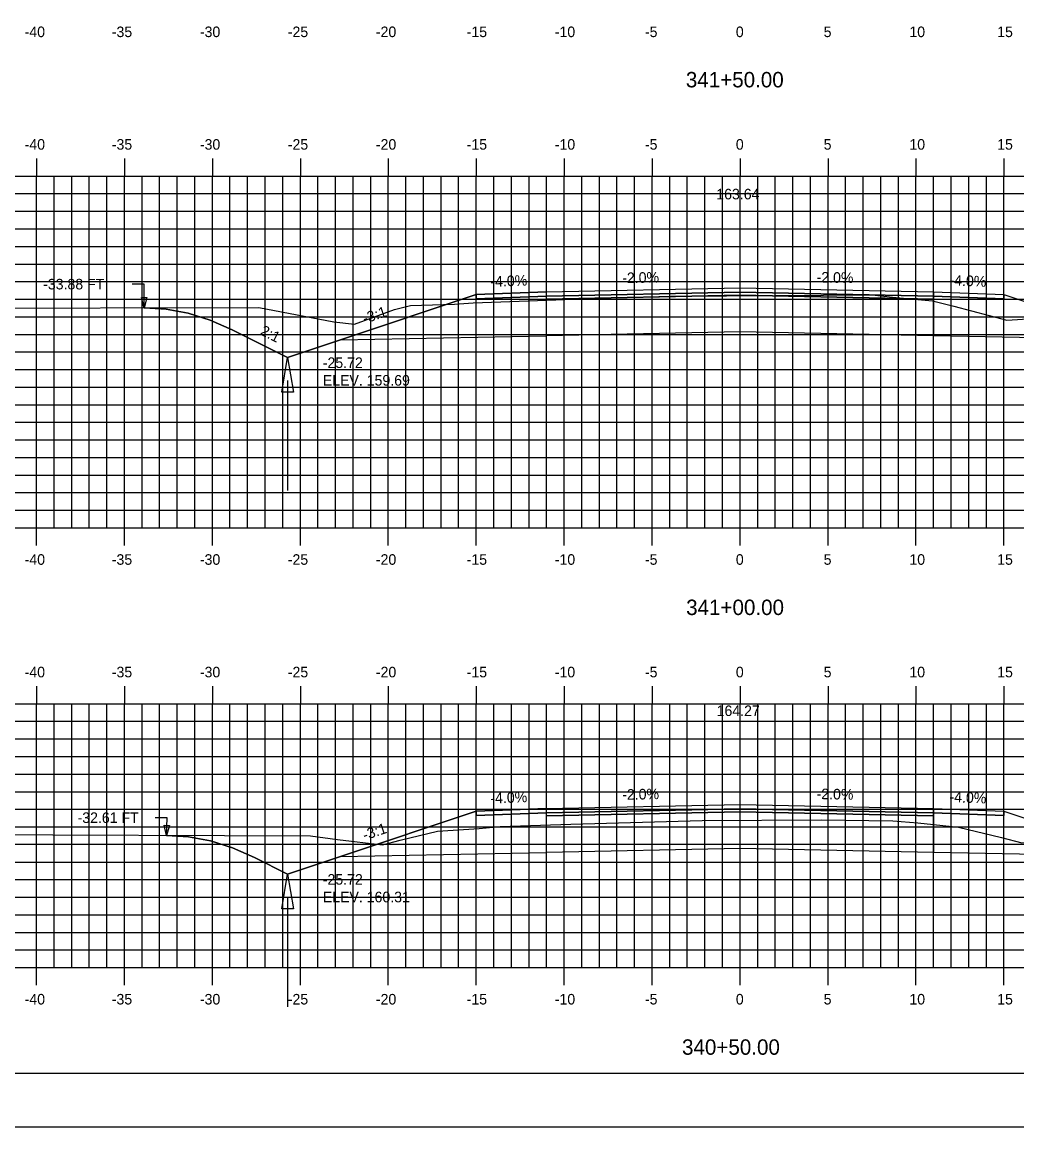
# Model space of a CAD drawing. Extents: x 1142976 to 1143146, y 608981 to 609091.
# Drawn here: x 1143018.7 to 1143075.3, y 608981.3 to 609044.1 of the extents above; entities that cross this region are included whole.
import ezdxf

# ---------------------------------------------------------------- set-up
doc = ezdxf.new("R2010")
doc.units = 0
for name, color, linetype in [('ANNOTATION', 7, 'Continuous'), ('BORDER', 7, 'Continuous'), ('D_Drainage_Ditch_Line', 7, 'Continuous'), ('D_Roadway_Centerline', 7, 'Continuous'), ('D_Roadway_Centerline_Text', 7, 'Continuous'), ('D_Roadway_Edge_Shoulder', 7, 'Continuous'), ('D_Roadway_Edge_TW', 7, 'Continuous'), ('D_Roadway_Pavement', 7, 'Continuous'), ('D_Roadway_SlopeLines', 7, 'Continuous'), ('D_Roadway_SubGrade', 7, 'Continuous'), ('D_Text_Standard', 7, 'Continuous'), ('H_V ANNOTATION', 7, 'Continuous'), ('MAJOR', 7, 'Continuous'), ('MINOR', 7, 'Continuous'), ('PLOT BOUNDARY', 7, 'Continuous'), ('S_Roadway_Centerline', 7, 'Continuous')]:
    doc.layers.add(name, color=color, linetype=linetype)

msp = doc.modelspace()

# ---------------------------------------------------------------- linework, layer by layer
for points in [[(1143025.688, 609027.847), (1143026.938, 609027.77), (1143028.188, 609027.537), (1143029.438, 609027.147), (1143030.688, 609026.6), (1143033.842, 609025.023), (1143036.842, 609026.023), (1143044.566, 609028.598), (1143044.567, 609028.598), (1143048.567, 609028.758), (1143059.567, 609028.978), (1143070.567, 609028.758), (1143074.567, 609028.598), (1143082.29, 609026.023), (1143085.29, 609025.023), (1143087.35, 609026.053), (1143088.6, 609026.598), (1143089.85, 609026.983), (1143091.1, 609027.207), (1143092.35, 609027.271)], [(1143026.958, 608997.852), (1143028.208, 608997.769), (1143029.458, 608997.532), (1143030.708, 608997.139), (1143031.958, 608996.592), (1143033.842, 608995.649), (1143036.842, 608996.649), (1143044.566, 608999.224), (1143044.567, 608999.224), (1143048.567, 608999.384), (1143059.567, 608999.604), (1143070.567, 608999.384), (1143074.567, 608999.224), (1143082.29, 608996.65), (1143085.29, 608995.65), (1143086.768, 608996.388), (1143088.018, 608996.934), (1143089.268, 608997.32), (1143090.518, 608997.546), (1143091.768, 608997.614)]]:
    msp.add_lwpolyline(points)
at = {"layer": 'BORDER'}
msp.add_lwpolyline([(1142984.567, 608984.335), (1143144.567, 608984.335), (1143144.567, 609089.335), (1142984.567, 609089.335)], close=True, dxfattribs=at)
at = {"layer": 'D_Drainage_Ditch_Line'}
for p, q in [((1143033.842, 609023.711), (1143033.842, 609017.467)), ((1143033.842, 608994.337), (1143033.842, 608988.094))]:
    msp.add_line(p, q, dxfattribs=at)
for points in [[(1143034.17, 609023.055), (1143033.514, 609023.055), (1143033.842, 609025.023)], [(1143034.17, 608993.681), (1143033.514, 608993.681), (1143033.842, 608995.649)]]:
    msp.add_lwpolyline(points, close=True, dxfattribs=at)
at = {"layer": 'D_Roadway_Edge_Shoulder'}
for points in [[(1143048.567, 609028.758), (1143044.567, 609028.598), (1143044.567, 609028.348), (1143048.567, 609028.508)], [(1143070.567, 609028.758), (1143074.567, 609028.598), (1143074.567, 609028.348), (1143070.567, 609028.508)], [(1143048.567, 608999.384), (1143044.567, 608999.224), (1143044.567, 608998.974), (1143048.567, 608999.134)], [(1143070.567, 608999.384), (1143074.567, 608999.224), (1143074.567, 608998.974), (1143070.567, 608999.134)]]:
    msp.add_lwpolyline(points, close=True, dxfattribs=at)
at = {"layer": 'D_Roadway_Edge_TW'}
for points in [[(1143048.567, 609028.508), (1143048.567, 609028.758), (1143059.567, 609028.978), (1143070.567, 609028.758), (1143070.567, 609028.508), (1143059.567, 609028.728)], [(1143048.567, 608999.134), (1143048.567, 608999.384), (1143059.567, 608999.604), (1143070.567, 608999.384), (1143070.567, 608999.134), (1143059.567, 608999.354)]]:
    msp.add_lwpolyline(points, close=True, dxfattribs=at)
at = {"layer": 'D_Roadway_Pavement'}
for points in [[(1143048.567, 609028.341), (1143048.567, 609028.508), (1143059.567, 609028.728), (1143070.567, 609028.508), (1143070.567, 609028.341), (1143059.567, 609028.561)], [(1143048.567, 608998.967), (1143048.567, 608999.134), (1143059.567, 608999.354), (1143070.567, 608999.134), (1143070.567, 608998.967), (1143059.567, 608999.187)]]:
    msp.add_lwpolyline(points, close=True, dxfattribs=at)
at = {"layer": 'D_Roadway_SlopeLines'}
for points in [[(1143033.842, 609025.023), (1143030.688, 609026.6), (1143029.438, 609027.147), (1143028.188, 609027.537), (1143026.938, 609027.77), (1143025.688, 609027.847)], [(1143036.842, 609026.023), (1143033.842, 609025.023)], [(1143033.842, 608995.649), (1143031.958, 608996.592), (1143030.708, 608997.139), (1143029.458, 608997.532), (1143028.208, 608997.769), (1143026.958, 608997.852)], [(1143036.842, 608996.649), (1143033.842, 608995.649)]]:
    msp.add_lwpolyline(points, dxfattribs=at)
at = {"layer": 'D_Roadway_SubGrade'}
for points in [[(1143048.567, 609028.341), (1143048.567, 609028.508), (1143044.567, 609028.348), (1143044.567, 609028.598), (1143044.566, 609028.598), (1143036.842, 609026.023), (1143048.567, 609026.258)], [(1143070.567, 609028.341), (1143070.567, 609028.508), (1143074.567, 609028.348), (1143074.567, 609028.598), (1143074.567, 609028.598), (1143082.29, 609026.023), (1143070.567, 609026.258)], [(1143048.567, 609026.258), (1143048.567, 609028.341), (1143059.567, 609028.561), (1143070.567, 609028.341), (1143070.567, 609026.258), (1143059.567, 609026.478)], [(1143048.567, 608998.967), (1143048.567, 608999.134), (1143044.567, 608998.974), (1143044.567, 608999.224), (1143044.566, 608999.224), (1143036.842, 608996.649), (1143048.567, 608996.884)], [(1143048.567, 608996.884), (1143048.567, 608998.967), (1143059.567, 608999.187), (1143070.567, 608998.967), (1143070.567, 608996.884), (1143059.567, 608997.104)], [(1143070.567, 608998.967), (1143070.567, 608999.134), (1143074.567, 608998.974), (1143074.567, 608999.224), (1143074.567, 608999.224), (1143082.29, 608996.65), (1143070.567, 608996.884)]]:
    msp.add_lwpolyline(points, close=True, dxfattribs=at)
at = {"layer": 'D_Text_Standard'}
for points in [[(1143025.688, 609027.85), (1143025.683, 609029.19), (1143025.003, 609029.19)], [(1143026.958, 608997.842), (1143026.986, 608998.856), (1143026.306, 608998.856)]]:
    msp.add_lwpolyline(points, dxfattribs=at)
for points in [[(1143025.688, 609027.85), (1143025.54, 609028.432), (1143025.831, 609028.433)], [(1143026.958, 608997.842), (1143026.828, 608998.427), (1143027.119, 608998.419)]]:
    msp.add_lwpolyline(points, close=True, dxfattribs=at)
at = {"layer": 'MAJOR'}
for p, q in [((1143019.567, 609036.337), (1143019.567, 609035.335)), ((1143024.567, 609036.337), (1143024.567, 609035.335)), ((1143029.567, 609036.337), (1143029.567, 609035.335)), ((1143034.567, 609036.337), (1143034.567, 609035.335)), ((1143039.567, 609036.337), (1143039.567, 609035.335)), ((1143044.567, 609036.337), (1143044.567, 609035.335)), ((1143049.567, 609036.337), (1143049.567, 609035.335)), ((1143054.567, 609036.337), (1143054.567, 609035.335)), ((1143059.567, 609036.337), (1143059.567, 609035.335)), ((1143064.567, 609036.337), (1143064.567, 609035.335)), ((1143069.567, 609036.337), (1143069.567, 609035.335)), ((1143074.567, 609036.337), (1143074.567, 609035.335)), ((1142989.567, 609035.335), (1143129.567, 609035.335)), ((1142989.567, 609035.335), (1143129.567, 609035.335)), ((1143019.567, 609015.335), (1143019.567, 609035.335)), ((1143024.567, 609015.335), (1143024.567, 609035.335)), ((1143029.567, 609015.335), (1143029.567, 609035.335)), ((1143034.567, 609015.335), (1143034.567, 609035.335)), ((1143039.567, 609015.335), (1143039.567, 609035.335)), ((1143044.567, 609015.335), (1143044.567, 609035.335)), ((1143049.567, 609015.335), (1143049.567, 609035.335)), ((1143054.567, 609015.335), (1143054.567, 609035.335)), ((1143059.567, 609015.335), (1143059.567, 609035.335)), ((1143064.567, 609015.335), (1143064.567, 609035.335)), ((1143069.567, 609015.335), (1143069.567, 609035.335)), ((1143074.567, 609015.335), (1143074.567, 609035.335)), ((1142989.567, 609030.335), (1143129.567, 609030.335)), ((1142989.567, 609025.335), (1143129.567, 609025.335)), ((1142989.567, 609020.335), (1143129.567, 609020.335)), ((1142989.567, 609015.335), (1143129.567, 609015.335)), ((1142989.567, 609015.335), (1143129.567, 609015.335)), ((1143019.567, 609014.333), (1143019.567, 609015.335)), ((1143024.567, 609014.333), (1143024.567, 609015.335)), ((1143029.567, 609014.333), (1143029.567, 609015.335)), ((1143034.567, 609014.333), (1143034.567, 609015.335)), ((1143039.567, 609014.333), (1143039.567, 609015.335)), ((1143044.567, 609014.333), (1143044.567, 609015.335)), ((1143049.567, 609014.333), (1143049.567, 609015.335)), ((1143054.567, 609014.333), (1143054.567, 609015.335)), ((1143059.567, 609014.333), (1143059.567, 609015.335)), ((1143064.567, 609014.333), (1143064.567, 609015.335)), ((1143069.567, 609014.333), (1143069.567, 609015.335)), ((1143074.567, 609014.333), (1143074.567, 609015.335)), ((1143019.567, 609006.337), (1143019.567, 609005.335)), ((1143024.567, 609006.337), (1143024.567, 609005.335)), ((1143029.567, 609006.337), (1143029.567, 609005.335)), ((1143034.567, 609006.337), (1143034.567, 609005.335)), ((1143039.567, 609006.337), (1143039.567, 609005.335)), ((1143044.567, 609006.337), (1143044.567, 609005.335)), ((1143049.567, 609006.337), (1143049.567, 609005.335)), ((1143054.567, 609006.337), (1143054.567, 609005.335)), ((1143059.567, 609006.337), (1143059.567, 609005.335)), ((1143064.567, 609006.337), (1143064.567, 609005.335)), ((1143069.567, 609006.337), (1143069.567, 609005.335)), ((1143074.567, 609006.337), (1143074.567, 609005.335)), ((1142989.567, 609005.335), (1143129.567, 609005.335)), ((1142989.567, 609005.335), (1143129.567, 609005.335)), ((1143019.567, 608990.335), (1143019.567, 609005.335)), ((1143024.567, 608990.335), (1143024.567, 609005.335)), ((1143029.567, 608990.335), (1143029.567, 609005.335)), ((1143034.567, 608990.335), (1143034.567, 609005.335)), ((1143039.567, 608990.335), (1143039.567, 609005.335)), ((1143044.567, 608990.335), (1143044.567, 609005.335)), ((1143049.567, 608990.335), (1143049.567, 609005.335)), ((1143054.567, 608990.335), (1143054.567, 609005.335)), ((1143059.567, 608990.335), (1143059.567, 609005.335)), ((1143064.567, 608990.335), (1143064.567, 609005.335)), ((1143069.567, 608990.335), (1143069.567, 609005.335)), ((1143074.567, 608990.335), (1143074.567, 609005.335)), ((1142989.567, 609000.335), (1143129.567, 609000.335)), ((1142989.567, 608995.335), (1143129.567, 608995.335)), ((1142989.567, 608990.335), (1143129.567, 608990.335)), ((1142989.567, 608990.335), (1143129.567, 608990.335)), ((1143019.567, 608989.333), (1143019.567, 608990.335)), ((1143024.567, 608989.333), (1143024.567, 608990.335)), ((1143029.567, 608989.333), (1143029.567, 608990.335)), ((1143034.567, 608989.333), (1143034.567, 608990.335)), ((1143039.567, 608989.333), (1143039.567, 608990.335)), ((1143044.567, 608989.333), (1143044.567, 608990.335)), ((1143049.567, 608989.333), (1143049.567, 608990.335)), ((1143054.567, 608989.333), (1143054.567, 608990.335)), ((1143059.567, 608989.333), (1143059.567, 608990.335)), ((1143064.567, 608989.333), (1143064.567, 608990.335)), ((1143069.567, 608989.333), (1143069.567, 608990.335)), ((1143074.567, 608989.333), (1143074.567, 608990.335))]:
    msp.add_line(p, q, dxfattribs=at)
at = {"layer": 'MINOR'}
for p, q in [((1143020.567, 609015.335), (1143020.567, 609035.335)), ((1143021.567, 609015.335), (1143021.567, 609035.335)), ((1143022.567, 609015.335), (1143022.567, 609035.335)), ((1143023.567, 609015.335), (1143023.567, 609035.335)), ((1143025.567, 609015.335), (1143025.567, 609035.335)), ((1143026.567, 609015.335), (1143026.567, 609035.335)), ((1143027.567, 609015.335), (1143027.567, 609035.335)), ((1143028.567, 609015.335), (1143028.567, 609035.335)), ((1143030.567, 609015.335), (1143030.567, 609035.335)), ((1143031.567, 609015.335), (1143031.567, 609035.335)), ((1143032.567, 609015.335), (1143032.567, 609035.335)), ((1143033.567, 609015.335), (1143033.567, 609035.335)), ((1143035.567, 609015.335), (1143035.567, 609035.335)), ((1143036.567, 609015.335), (1143036.567, 609035.335)), ((1143037.567, 609015.335), (1143037.567, 609035.335)), ((1143038.567, 609015.335), (1143038.567, 609035.335)), ((1143040.567, 609015.335), (1143040.567, 609035.335)), ((1143041.567, 609015.335), (1143041.567, 609035.335)), ((1143042.567, 609015.335), (1143042.567, 609035.335)), ((1143043.567, 609015.335), (1143043.567, 609035.335)), ((1143045.567, 609015.335), (1143045.567, 609035.335)), ((1143046.567, 609015.335), (1143046.567, 609035.335)), ((1143047.567, 609015.335), (1143047.567, 609035.335)), ((1143048.567, 609015.335), (1143048.567, 609035.335)), ((1143050.567, 609015.335), (1143050.567, 609035.335)), ((1143051.567, 609015.335), (1143051.567, 609035.335)), ((1143052.567, 609015.335), (1143052.567, 609035.335)), ((1143053.567, 609015.335), (1143053.567, 609035.335)), ((1143055.567, 609015.335), (1143055.567, 609035.335)), ((1143056.567, 609015.335), (1143056.567, 609035.335)), ((1143057.567, 609015.335), (1143057.567, 609035.335)), ((1143058.567, 609015.335), (1143058.567, 609035.335)), ((1143060.567, 609015.335), (1143060.567, 609035.335)), ((1143061.567, 609015.335), (1143061.567, 609035.335)), ((1143062.567, 609015.335), (1143062.567, 609035.335)), ((1143063.567, 609015.335), (1143063.567, 609035.335)), ((1143065.567, 609015.335), (1143065.567, 609035.335)), ((1143066.567, 609015.335), (1143066.567, 609035.335)), ((1143067.567, 609015.335), (1143067.567, 609035.335)), ((1143068.567, 609015.335), (1143068.567, 609035.335)), ((1143070.567, 609015.335), (1143070.567, 609035.335)), ((1143071.567, 609015.335), (1143071.567, 609035.335)), ((1143072.567, 609015.335), (1143072.567, 609035.335)), ((1143073.567, 609015.335), (1143073.567, 609035.335)), ((1142989.567, 609034.335), (1143129.567, 609034.335)), ((1142989.567, 609033.335), (1143129.567, 609033.335)), ((1142989.567, 609032.335), (1143129.567, 609032.335)), ((1142989.567, 609031.335), (1143129.567, 609031.335)), ((1142989.567, 609029.335), (1143129.567, 609029.335)), ((1142989.567, 609028.335), (1143129.567, 609028.335)), ((1142989.567, 609027.335), (1143129.567, 609027.335)), ((1142989.567, 609026.335), (1143129.567, 609026.335)), ((1142989.567, 609024.335), (1143129.567, 609024.335)), ((1142989.567, 609023.335), (1143129.567, 609023.335)), ((1142989.567, 609022.335), (1143129.567, 609022.335)), ((1142989.567, 609021.335), (1143129.567, 609021.335)), ((1142989.567, 609019.335), (1143129.567, 609019.335)), ((1142989.567, 609018.335), (1143129.567, 609018.335)), ((1142989.567, 609017.335), (1143129.567, 609017.335)), ((1142989.567, 609016.335), (1143129.567, 609016.335)), ((1143020.567, 608990.335), (1143020.567, 609005.335)), ((1143021.567, 608990.335), (1143021.567, 609005.335)), ((1143022.567, 608990.335), (1143022.567, 609005.335)), ((1143023.567, 608990.335), (1143023.567, 609005.335)), ((1143025.567, 608990.335), (1143025.567, 609005.335)), ((1143026.567, 608990.335), (1143026.567, 609005.335)), ((1143027.567, 608990.335), (1143027.567, 609005.335)), ((1143028.567, 608990.335), (1143028.567, 609005.335)), ((1143030.567, 608990.335), (1143030.567, 609005.335)), ((1143031.567, 608990.335), (1143031.567, 609005.335)), ((1143032.567, 608990.335), (1143032.567, 609005.335)), ((1143033.567, 608990.335), (1143033.567, 609005.335)), ((1143035.567, 608990.335), (1143035.567, 609005.335)), ((1143036.567, 608990.335), (1143036.567, 609005.335)), ((1143037.567, 608990.335), (1143037.567, 609005.335)), ((1143038.567, 608990.335), (1143038.567, 609005.335)), ((1143040.567, 608990.335), (1143040.567, 609005.335)), ((1143041.567, 608990.335), (1143041.567, 609005.335)), ((1143042.567, 608990.335), (1143042.567, 609005.335)), ((1143043.567, 608990.335), (1143043.567, 609005.335)), ((1143045.567, 608990.335), (1143045.567, 609005.335)), ((1143046.567, 608990.335), (1143046.567, 609005.335)), ((1143047.567, 608990.335), (1143047.567, 609005.335)), ((1143048.567, 608990.335), (1143048.567, 609005.335)), ((1143050.567, 608990.335), (1143050.567, 609005.335)), ((1143051.567, 608990.335), (1143051.567, 609005.335)), ((1143052.567, 608990.335), (1143052.567, 609005.335)), ((1143053.567, 608990.335), (1143053.567, 609005.335)), ((1143055.567, 608990.335), (1143055.567, 609005.335)), ((1143056.567, 608990.335), (1143056.567, 609005.335)), ((1143057.567, 608990.335), (1143057.567, 609005.335)), ((1143058.567, 608990.335), (1143058.567, 609005.335)), ((1143060.567, 608990.335), (1143060.567, 609005.335)), ((1143061.567, 608990.335), (1143061.567, 609005.335)), ((1143062.567, 608990.335), (1143062.567, 609005.335)), ((1143063.567, 608990.335), (1143063.567, 609005.335)), ((1143065.567, 608990.335), (1143065.567, 609005.335)), ((1143066.567, 608990.335), (1143066.567, 609005.335)), ((1143067.567, 608990.335), (1143067.567, 609005.335)), ((1143068.567, 608990.335), (1143068.567, 609005.335)), ((1143070.567, 608990.335), (1143070.567, 609005.335)), ((1143071.567, 608990.335), (1143071.567, 609005.335)), ((1143072.567, 608990.335), (1143072.567, 609005.335)), ((1143073.567, 608990.335), (1143073.567, 609005.335)), ((1142989.567, 609004.335), (1143129.567, 609004.335)), ((1142989.567, 609003.335), (1143129.567, 609003.335)), ((1142989.567, 609002.335), (1143129.567, 609002.335)), ((1142989.567, 609001.335), (1143129.567, 609001.335)), ((1142989.567, 608999.335), (1143129.567, 608999.335)), ((1142989.567, 608998.335), (1143129.567, 608998.335)), ((1143129.567, 608997.335), (1142989.567, 608997.335)), ((1142989.567, 608996.335), (1143129.567, 608996.335)), ((1142989.567, 608994.335), (1143129.567, 608994.335)), ((1142989.567, 608993.335), (1143129.567, 608993.335)), ((1142989.567, 608992.335), (1143129.567, 608992.335)), ((1142989.567, 608991.335), (1143129.567, 608991.335))]:
    msp.add_line(p, q, dxfattribs=at)
at = {"layer": 'PLOT BOUNDARY'}
msp.add_lwpolyline([(1142976.473, 608981.276), (1143146.473, 608981.276), (1143146.473, 609091.276), (1142976.473, 609091.276)], close=True, dxfattribs=at)
at = {"layer": 'S_Roadway_Centerline'}
for points in [[(1142989.567, 609027.545), (1142996.316, 609027.669), (1143012.235, 609027.85), (1143014.156, 609027.829), (1143032.215, 609027.857), (1143036.466, 609027.056), (1143037.644, 609026.918), (1143039.915, 609027.744), (1143040.829, 609027.969), (1143043.332, 609028.06), (1143044.384, 609028.129), (1143052.209, 609028.413), (1143055.628, 609028.504), (1143058.799, 609028.519), (1143067.081, 609028.581), (1143068.236, 609028.458), (1143070.515, 609028.236), (1143071.722, 609027.944), (1143074.732, 609027.136), (1143077.419, 609027.321)], [(1142989.567, 608997.913), (1143015.23, 608997.899), (1143015.369, 608997.901), (1143015.581, 608997.899), (1143035.144, 608997.818), (1143036.675, 608997.612), (1143039.235, 608997.313), (1143040.24, 608997.57), (1143042.363, 608998.094), (1143044.738, 608998.247), (1143045.936, 608998.359), (1143049.94, 608998.493), (1143057.403, 608998.694), (1143064.179, 608998.728), (1143068.256, 608998.668), (1143069.663, 608998.56), (1143071.984, 608998.313), (1143074.42, 608997.723), (1143075.581, 608997.422), (1143077.949, 608997.561), (1143080.787, 608997.747), (1143089.847, 608997.631), (1143111.617, 608997.433), (1143129.567, 608997.446)]]:
    msp.add_lwpolyline(points, dxfattribs=at)

# ---------------------------------------------------------------- texts
at = {"layer": 'ANNOTATION'}
for s, rotation, p in [('-2.0%', 1.14576, (1143052.87, 609029.244)), ('-2.0%', 358.85424, (1143063.91, 609029.291)), ('-4.0%', 2.29061, (1143045.382, 609029.031)), ('-4.0%', 357.70939, (1143071.462, 609029.123)), ('-3:1', 18.43482, (1143038.221, 609026.937)), ('2:1', 333.43495, (1143032.232, 609026.346)), ('-4.0%', 2.29061, (1143045.382, 608999.657)), ('-2.0%', 1.14576, (1143052.87, 608999.87)), ('-2.0%', 358.85424, (1143063.91, 608999.917)), ('-4.0%', 357.70939, (1143071.462, 608999.749)), ('-3:1', 18.43482, (1143038.221, 608997.563))]:
    msp.add_text(s, height=0.6, rotation=rotation, dxfattribs=at).set_placement(p)
at = {"layer": 'D_Roadway_Centerline'}
for s, p in [('C', (1143059.561, 609028.978)), ('L', (1143059.567, 609028.971)), ('C', (1143059.561, 608999.604)), ('L', (1143059.567, 608999.597))]:
    msp.add_text(s, height=0.0146, dxfattribs=at).set_placement(p)
at = {"layer": 'D_Roadway_Centerline_Text'}
for s, p in [('163.64', (1143058.213, 609034.01)), ('164.27', (1143058.234, 609004.636))]:
    msp.add_text(s, height=0.6, dxfattribs=at).set_placement(p)
at = {"layer": 'D_Text_Standard'}
for s, p in [('-33.88 FT', (1143019.944, 609028.89)), ('-25.72', (1143035.842, 609024.423)), ('ELEV. 159.69', (1143035.842, 609023.421)), ('-32.61 FT', (1143021.9, 608998.556)), ('-25.72', (1143035.842, 608995.049)), ('ELEV. 160.31', (1143035.842, 608994.047))]:
    msp.add_text(s, height=0.6, dxfattribs=at).set_placement(p)
at = {"layer": 'H_V ANNOTATION'}
for s, height, p in [('-40', 0.6, (1143018.892, 609043.235)), ('-35', 0.6, (1143023.847, 609043.235)), ('-30', 0.6, (1143028.855, 609043.235)), ('-25', 0.6, (1143033.852, 609043.235)), ('-20', 0.6, (1143038.86, 609043.235)), ('-15', 0.6, (1143044.023, 609043.235)), ('-10', 0.6, (1143049.031, 609043.235)), ('-5', 0.6, (1143054.157, 609043.235)), ('0', 0.6, (1143059.326, 609043.235)), ('5', 0.6, (1143064.318, 609043.235)), ('10', 0.6, (1143069.192, 609043.235)), ('15', 0.6, (1143074.184, 609043.235)), ('341+50.00', 0.875, (1143056.484, 609040.378)), ('-40', 0.6, (1143018.892, 609036.835)), ('-35', 0.6, (1143023.847, 609036.835)), ('-30', 0.6, (1143028.855, 609036.835)), ('-25', 0.6, (1143033.852, 609036.835)), ('-20', 0.6, (1143038.86, 609036.835)), ('-15', 0.6, (1143044.023, 609036.835)), ('-10', 0.6, (1143049.031, 609036.835)), ('-5', 0.6, (1143054.157, 609036.835)), ('0', 0.6, (1143059.326, 609036.835)), ('5', 0.6, (1143064.318, 609036.835)), ('10', 0.6, (1143069.192, 609036.835)), ('15', 0.6, (1143074.184, 609036.835)), ('-40', 0.6, (1143018.892, 609013.235)), ('-35', 0.6, (1143023.847, 609013.235)), ('-30', 0.6, (1143028.855, 609013.235)), ('-25', 0.6, (1143033.852, 609013.235)), ('-20', 0.6, (1143038.86, 609013.235)), ('-15', 0.6, (1143044.023, 609013.235)), ('-10', 0.6, (1143049.031, 609013.235)), ('-5', 0.6, (1143054.157, 609013.235)), ('0', 0.6, (1143059.326, 609013.235)), ('5', 0.6, (1143064.318, 609013.235)), ('10', 0.6, (1143069.192, 609013.235)), ('15', 0.6, (1143074.184, 609013.235)), ('341+00.00', 0.875, (1143056.5, 609010.378)), ('-40', 0.6, (1143018.892, 609006.835)), ('-35', 0.6, (1143023.847, 609006.835)), ('-30', 0.6, (1143028.855, 609006.835)), ('-25', 0.6, (1143033.852, 609006.835)), ('-20', 0.6, (1143038.86, 609006.835)), ('-15', 0.6, (1143044.023, 609006.835)), ('-10', 0.6, (1143049.031, 609006.835)), ('-5', 0.6, (1143054.157, 609006.835)), ('0', 0.6, (1143059.326, 609006.835)), ('5', 0.6, (1143064.318, 609006.835)), ('10', 0.6, (1143069.192, 609006.835)), ('15', 0.6, (1143074.184, 609006.835)), ('-40', 0.6, (1143018.892, 608988.235)), ('-35', 0.6, (1143023.847, 608988.235)), ('-30', 0.6, (1143028.855, 608988.235)), ('-25', 0.6, (1143033.852, 608988.235)), ('-20', 0.6, (1143038.86, 608988.235)), ('-15', 0.6, (1143044.023, 608988.235)), ('-10', 0.6, (1143049.031, 608988.235)), ('-5', 0.6, (1143054.157, 608988.235)), ('0', 0.6, (1143059.326, 608988.235)), ('5', 0.6, (1143064.318, 608988.235)), ('10', 0.6, (1143069.192, 608988.235)), ('15', 0.6, (1143074.184, 608988.235)), ('340+50.00', 0.875, (1143056.266, 608985.378))]:
    msp.add_text(s, height=height, dxfattribs=at).set_placement(p)
at = {"layer": 'S_Roadway_Centerline'}
for s, p in [('L', (1143055.619, 609028.497)), ('C', (1143055.622, 609028.504)), ('L', (1143057.394, 608998.687)), ('C', (1143057.397, 608998.694))]:
    msp.add_text(s, height=0.0146, dxfattribs=at).set_placement(p)

doc.saveas('drawing.dxf')
